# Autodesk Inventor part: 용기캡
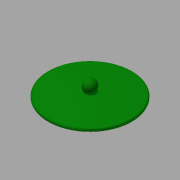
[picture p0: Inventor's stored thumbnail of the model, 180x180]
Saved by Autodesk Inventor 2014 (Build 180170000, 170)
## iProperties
Created: 2018-01
Part Number: 용기캡
Material: ABS 플라스틱
Document SubType Name: Modeling
Designer: mduedu
Density: 1 g/cm^3
Appearance: 진녹색
Author: mduedu
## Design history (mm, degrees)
sketch "스케치1"
  geometry: L1 (-35, 2.5)-(0, 2.5); L2 (0, 5)-(0, 0); L3 (0, 0)-(-35, 0); L4 (-35, 0)-(-35, 2.5); L5 (-31, 0)-(-29, 0); L6 (-29, 0)-(-29, -2); L7 (-29, -2)-(-31, -2); L8 (-31, -2)-(-31, 0); A1 r 246.25 centre (0, -241.25) between (0, 5) and (-35, 2.5); 1 further point
  constraints: 16 end point, 4 parallel, 2 horizontal, 2 perpendicular, 2 point on circle, 1 centre point, 1 coincident, 1 midpoint, 1 point on line, 1 vertical alignment
  dimensions: "d2" = 70 diameter of L4 L2; "d3" = 5 distance from line of L2.start L3; "d4" = 2.5 distance of L3.end L1.start; "d5" = 4 distance between parallel lines of L8 L4; "d6" = 2 distance of L6.end L7.end; "d7" = 2 distance between parallel lines of L7 L3
revolve "회전1" sketch "스케치1" stored, may be unused: angle "d8" = 90 deg
chamfer "모따기1" distance "d9" = 0.5; stored, may be unused: second distance "d10" = 2, angle "d11" = 45 deg
fillet "모깎기1" dims "d12" = 1
fillet "모깎기2" dims "d13" = 1
sketch "스케치2"
  geometry: L1 (-30.5, -2)-(-31, -1.5) reference; L2 (-31, -1.5)-(-31, 0) reference; L3 (-31, 0)-(-34, 0) reference; L4 (-35, 1)-(-35, 1.632) reference; L5 (35, 1.632)-(35, 1) reference; L6 (34, 0)-(31, 0) reference; L7 (31, 0)-(31, -1.5) reference; L8 (31, -1.5)-(30.5, -2) reference; L9 (30.5, -2)-(29, -2) reference; L10 (29, -2)-(29, -1) reference; L11 (28, 0)-(-28, 0) reference; L12 (-29, -1)-(-29, -2) reference; L13 (-29, -2)-(-30.5, -2) reference; L14 (0, 14)-(0, 4); A1 r 1 centre (-34, 1) between (-35, 1) and (-34, 0) reference; A2 r 1 centre (-34, 1.632) between (-34.139, 2.622) and (-35, 1.632) reference; A3 r 246.25 centre (0, -241.25) between (34.139, 2.622) and (-34.139, 2.622) reference; A4 r 1 centre (34, 1.632) between (35, 1.632) and (34.139, 2.622) reference; A5 r 1 centre (34, 1) between (34, 0) and (35, 1) reference; A6 r 1 centre (28, -1) between (29, -1) and (28, 0) reference; A7 r 1 centre (-28, -1) between (-28, 0) and (-29, -1) reference; A8 r 5 centre (0, 9) between (0, 14) and (0, 4); 3 further points
  constraints: 2 end point, 2 midpoint, 2 point on circle, 1 centre point, 1 coincident, 1 perpendicular, 1 point on line, 1 vertical alignment
  dimensions: "d14" = 10 diameter of A8; "d16" = 9 distance of A8.centre point (0, 0)
revolve "회전2" sketch "스케치2" stored, may be unused: angle "d17" = 90 deg
fillet "모깎기3" dims "d18" = 1
node "솔리드1"
node "절단 모서리 투영1"
